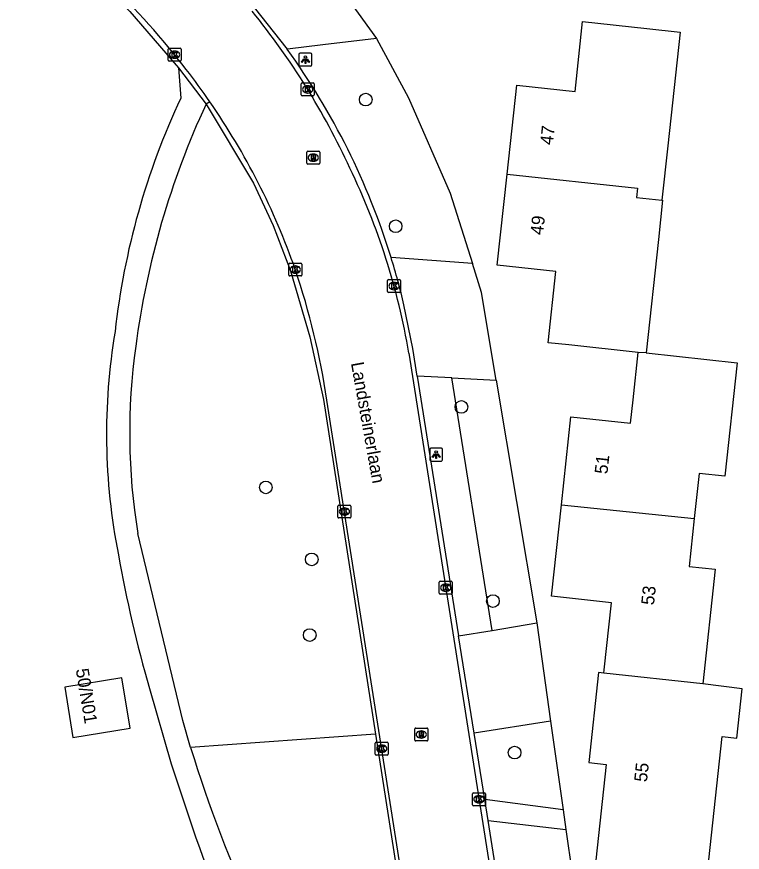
# Model space of a CAD drawing. Extents: x 162157 to 163165, y 378998 to 380775.
# Drawn here: x 162604.5 to 162660.6, y 380304.6 to 380369.3 of the extents above; entities that cross this region are included whole.
import ezdxf

# ---------------------------------------------------------------- set-up
doc = ezdxf.new("R2010")
doc.units = 0
for name, color, linetype in [('IMGEO_Berm_groen', 7, 'Continuous'), ('IMGEO_Boom', 7, 'Continuous'), ('IMGEO_Groenvoorziening', 7, 'Continuous'), ('IMGEO_Kolk', 7, 'Continuous'), ('IMGEO_Lichtpunt', 7, 'Continuous'), ('IMGEO_Naaldbos', 7, 'Continuous'), ('IMGEO_Openbare_ruimte_label', 7, 'Continuous'), ('IMGEO_Pand', 7, 'Continuous'), ('IMGEO_Pand_nummerreeks', 7, 'Continuous'), ('IMGEO_Rijbaan_lokaal_gesloten', 7, 'Continuous'), ('IMGEO_Rioolput', 7, 'Continuous'), ('IMGEO_Voetpad_halfverhard', 7, 'Continuous'), ('IMGEO_Voetpad_open', 7, 'Continuous')]:
    doc.layers.add(name, color=color, linetype=linetype)

msp = doc.modelspace()

# ---------------------------------------------------------------- linework, layer by layer
at = {"layer": 'IMGEO_Berm_groen'}
msp.add_lwpolyline([(162641.266, 380321.775), (162638.135, 380341.3)], dxfattribs=at)
at = {"layer": 'IMGEO_Boom'}
for centre in [(162631.474, 380362.838), (162633.792, 380353.035), (162638.883, 380339.056), (162623.744, 380332.835), (162627.298, 380327.261), (162641.318, 380324.036), (162627.144, 380321.407), (162642.991, 380312.317)]:
    msp.add_circle(centre, 0.489, dxfattribs=at)
at = {"layer": 'IMGEO_Groenvoorziening'}
for points in [[(162632.3, 380367.569), (162634.789, 380362.981), (162638.007, 380355.595), (162639.724, 380350.164)], [(162641.57, 380341.12), (162644.707, 380322.347)], [(162645.784, 380314.752), (162646.759, 380307.877)], [(162646.972, 380306.371), (162647.938, 380299.554)]]:
    msp.add_lwpolyline(points, dxfattribs=at)
at = {"layer": 'IMGEO_Kolk'}
for p, q in [((162616.255, 380366.813), (162617.107, 380366.813)), ((162616.18, 380365.887), (162616.18, 380366.739)), ((162616.668, 380366.593), (162616.693, 380366.593)), ((162617.181, 380366.739), (162617.181, 380365.887)), ((162617.107, 380365.813), (162616.255, 380365.813)), ((162616.691, 380366.033), (162616.666, 380366.033)), ((162626.488, 380363.201), (162626.488, 380364.053)), ((162626.563, 380364.127), (162627.415, 380364.127)), ((162626.976, 380363.907), (162627.001, 380363.907)), ((162627.489, 380364.053), (162627.489, 380363.201)), ((162627.415, 380363.127), (162626.563, 380363.127)), ((162626.999, 380363.347), (162626.974, 380363.347)), ((162625.523, 380349.264), (162625.523, 380350.116)), ((162625.598, 380350.19), (162626.45, 380350.19)), ((162626.524, 380350.116), (162626.524, 380349.264)), ((162626.034, 380349.41), (162626.009, 380349.41)), ((162626.011, 380349.97), (162626.036, 380349.97)), ((162626.45, 380349.19), (162625.598, 380349.19)), ((162633.169, 380347.984), (162633.169, 380348.836)), ((162633.244, 380348.91), (162634.096, 380348.91)), ((162633.657, 380348.69), (162633.682, 380348.69)), ((162634.17, 380348.836), (162634.17, 380347.984)), ((162633.68, 380348.13), (162633.655, 380348.13)), ((162634.096, 380347.91), (162633.244, 380347.91)), ((162629.325, 380330.542), (162629.325, 380331.394)), ((162629.4, 380331.468), (162630.252, 380331.468)), ((162629.813, 380331.248), (162629.838, 380331.248)), ((162630.326, 380331.394), (162630.326, 380330.542)), ((162629.836, 380330.688), (162629.811, 380330.688)), ((162630.252, 380330.468), (162629.4, 380330.468)), ((162637.164, 380324.644), (162637.164, 380325.496)), ((162637.239, 380325.57), (162638.091, 380325.57)), ((162638.165, 380325.496), (162638.165, 380324.644)), ((162637.675, 380324.79), (162637.65, 380324.79)), ((162637.652, 380325.35), (162637.677, 380325.35)), ((162638.091, 380324.57), (162637.239, 380324.57)), ((162632.209, 380312.197), (162632.209, 380313.049)), ((162632.284, 380313.123), (162633.136, 380313.123)), ((162632.697, 380312.903), (162632.722, 380312.903)), ((162633.21, 380313.049), (162633.21, 380312.197)), ((162633.136, 380312.123), (162632.284, 380312.123)), ((162632.72, 380312.343), (162632.695, 380312.343)), ((162639.737, 380308.284), (162639.737, 380309.136)), ((162639.812, 380309.21), (162640.664, 380309.21)), ((162640.225, 380308.99), (162640.25, 380308.99)), ((162640.738, 380309.136), (162640.738, 380308.284)), ((162640.664, 380308.21), (162639.812, 380308.21)), ((162640.248, 380308.43), (162640.223, 380308.43))]:
    msp.add_line(p, q, dxfattribs=at)
for points in [[(162616.255, 380366.813), (162617.107, 380366.813)], [(162616.18, 380365.887), (162616.18, 380366.739)], [(162616.501, 380366.513), (162616.624, 380366.513), (162616.624, 380366.362), (162616.754, 380366.513), (162616.918, 380366.513), (162616.772, 380366.362), (162616.925, 380366.113), (162616.773, 380366.113), (162616.688, 380366.277), (162616.624, 380366.21), (162616.624, 380366.113), (162616.501, 380366.113), (162616.501, 380366.513)], [(162617.181, 380366.739), (162617.181, 380365.887)], [(162617.107, 380365.813), (162616.255, 380365.813)], [(162626.488, 380363.201), (162626.488, 380364.053)], [(162626.563, 380364.127), (162627.415, 380364.127)], [(162626.809, 380363.827), (162626.932, 380363.827), (162626.932, 380363.676), (162627.062, 380363.827), (162627.226, 380363.827), (162627.08, 380363.676), (162627.233, 380363.427), (162627.081, 380363.427), (162626.996, 380363.591), (162626.932, 380363.524), (162626.932, 380363.427), (162626.809, 380363.427), (162626.809, 380363.827)], [(162627.489, 380364.053), (162627.489, 380363.201)], [(162627.415, 380363.127), (162626.563, 380363.127)], [(162625.523, 380349.264), (162625.523, 380350.116)], [(162625.598, 380350.19), (162626.45, 380350.19)], [(162626.524, 380350.116), (162626.524, 380349.264)], [(162625.844, 380349.89), (162625.967, 380349.89), (162625.967, 380349.739), (162626.097, 380349.89), (162626.261, 380349.89), (162626.115, 380349.739), (162626.268, 380349.49), (162626.116, 380349.49), (162626.031, 380349.654), (162625.967, 380349.587), (162625.967, 380349.49), (162625.844, 380349.49), (162625.844, 380349.89)], [(162626.45, 380349.19), (162625.598, 380349.19)], [(162633.169, 380347.984), (162633.169, 380348.836)], [(162633.244, 380348.91), (162634.096, 380348.91)], [(162634.17, 380348.836), (162634.17, 380347.984)], [(162633.49, 380348.61), (162633.613, 380348.61), (162633.613, 380348.459), (162633.743, 380348.61), (162633.907, 380348.61), (162633.761, 380348.459), (162633.914, 380348.21), (162633.762, 380348.21), (162633.677, 380348.374), (162633.613, 380348.307), (162633.613, 380348.21), (162633.49, 380348.21), (162633.49, 380348.61)], [(162634.096, 380347.91), (162633.244, 380347.91)], [(162629.325, 380330.542), (162629.325, 380331.394)], [(162629.4, 380331.468), (162630.252, 380331.468)], [(162630.326, 380331.394), (162630.326, 380330.542)], [(162629.646, 380331.168), (162629.769, 380331.168), (162629.769, 380331.017), (162629.899, 380331.168), (162630.063, 380331.168), (162629.917, 380331.017), (162630.07, 380330.768), (162629.918, 380330.768), (162629.833, 380330.932), (162629.769, 380330.865), (162629.769, 380330.768), (162629.646, 380330.768), (162629.646, 380331.168)], [(162630.252, 380330.468), (162629.4, 380330.468)], [(162637.164, 380324.644), (162637.164, 380325.496)], [(162637.239, 380325.57), (162638.091, 380325.57)], [(162638.165, 380325.496), (162638.165, 380324.644)], [(162637.485, 380325.27), (162637.608, 380325.27), (162637.608, 380325.119), (162637.738, 380325.27), (162637.902, 380325.27), (162637.756, 380325.119), (162637.909, 380324.87), (162637.757, 380324.87), (162637.672, 380325.034), (162637.608, 380324.967), (162637.608, 380324.87), (162637.485, 380324.87), (162637.485, 380325.27)], [(162638.091, 380324.57), (162637.239, 380324.57)], [(162632.209, 380312.197), (162632.209, 380313.049)], [(162632.284, 380313.123), (162633.136, 380313.123)], [(162632.53, 380312.823), (162632.653, 380312.823), (162632.653, 380312.672), (162632.783, 380312.823), (162632.947, 380312.823), (162632.801, 380312.672), (162632.954, 380312.423), (162632.802, 380312.423), (162632.717, 380312.587), (162632.653, 380312.52), (162632.653, 380312.423), (162632.53, 380312.423), (162632.53, 380312.823)], [(162633.21, 380313.049), (162633.21, 380312.197)], [(162633.136, 380312.123), (162632.284, 380312.123)], [(162639.737, 380308.284), (162639.737, 380309.136)], [(162639.812, 380309.21), (162640.664, 380309.21)], [(162640.058, 380308.91), (162640.181, 380308.91), (162640.181, 380308.759), (162640.311, 380308.91), (162640.475, 380308.91), (162640.329, 380308.759), (162640.482, 380308.51), (162640.33, 380308.51), (162640.245, 380308.674), (162640.181, 380308.607), (162640.181, 380308.51), (162640.058, 380308.51), (162640.058, 380308.91)], [(162640.738, 380309.136), (162640.738, 380308.284)], [(162640.664, 380308.21), (162639.812, 380308.21)]]:
    msp.add_lwpolyline(points, dxfattribs=at)
for centre, start, end in [((162616.257, 380366.737), 91.55205, 178.44795), ((162616.257, 380366.737), 91.55205, 178.44795), ((162617.105, 380366.737), 1.55205, 88.44795), ((162617.105, 380366.737), 1.55205, 88.44795), ((162616.257, 380365.889), 181.55205, 268.44795), ((162616.257, 380365.889), 181.55205, 268.44795), ((162617.105, 380365.889), 271.55205, 358.44795), ((162617.105, 380365.889), 271.55205, 358.44795), ((162626.565, 380364.051), 91.55205, 178.44795), ((162626.565, 380364.051), 91.55205, 178.44795), ((162627.413, 380364.051), 1.55205, 88.44795), ((162627.413, 380364.051), 1.55205, 88.44795), ((162626.565, 380363.203), 181.55205, 268.44795), ((162626.565, 380363.203), 181.55205, 268.44795), ((162627.413, 380363.203), 271.55205, 358.44795), ((162627.413, 380363.203), 271.55205, 358.44795), ((162625.6, 380350.114), 91.55205, 178.44795), ((162625.6, 380350.114), 91.55205, 178.44795), ((162626.448, 380350.114), 1.55205, 88.44795), ((162626.448, 380350.114), 1.55205, 88.44795), ((162625.6, 380349.266), 181.55205, 268.44795), ((162625.6, 380349.266), 181.55205, 268.44795), ((162626.448, 380349.266), 271.55205, 358.44795), ((162626.448, 380349.266), 271.55205, 358.44795), ((162633.246, 380348.834), 91.55205, 178.44795), ((162633.246, 380348.834), 91.55205, 178.44795), ((162634.094, 380348.834), 1.55205, 88.44795), ((162634.094, 380348.834), 1.55205, 88.44795), ((162633.246, 380347.986), 181.55205, 268.44795), ((162633.246, 380347.986), 181.55205, 268.44795), ((162634.094, 380347.986), 271.55205, 358.44795), ((162634.094, 380347.986), 271.55205, 358.44795), ((162629.402, 380331.392), 91.55205, 178.44795), ((162629.402, 380331.392), 91.55205, 178.44795), ((162630.25, 380331.392), 1.55205, 88.44795), ((162630.25, 380331.392), 1.55205, 88.44795), ((162629.402, 380330.544), 181.55205, 268.44795), ((162629.402, 380330.544), 181.55205, 268.44795), ((162630.25, 380330.544), 271.55205, 358.44795), ((162630.25, 380330.544), 271.55205, 358.44795), ((162637.241, 380325.494), 91.55205, 178.44795), ((162637.241, 380325.494), 91.55205, 178.44795), ((162638.089, 380325.494), 1.55205, 88.44795), ((162638.089, 380325.494), 1.55205, 88.44795), ((162637.241, 380324.646), 181.55205, 268.44795), ((162637.241, 380324.646), 181.55205, 268.44795), ((162638.089, 380324.646), 271.55205, 358.44795), ((162638.089, 380324.646), 271.55205, 358.44795), ((162632.286, 380313.047), 91.55205, 178.44795), ((162632.286, 380313.047), 91.55205, 178.44795), ((162633.134, 380313.047), 1.55205, 88.44795), ((162633.134, 380313.047), 1.55205, 88.44795), ((162632.286, 380312.199), 181.55205, 268.44795), ((162632.286, 380312.199), 181.55205, 268.44795), ((162633.134, 380312.199), 271.55205, 358.44795), ((162633.134, 380312.199), 271.55205, 358.44795), ((162639.814, 380309.134), 91.55205, 178.44795), ((162639.814, 380309.134), 91.55205, 178.44795), ((162640.662, 380309.134), 1.55205, 88.44795), ((162640.662, 380309.134), 1.55205, 88.44795), ((162639.814, 380308.286), 181.55205, 268.44795), ((162639.814, 380308.286), 181.55205, 268.44795), ((162640.662, 380308.286), 271.55205, 358.44795), ((162640.662, 380308.286), 271.55205, 358.44795)]:
    msp.add_arc(centre, 0.0765, start, end, dxfattribs=at)
for centre, major_axis, ratio, start_param, end_param in [((162616.667, 380366.313), (-0.387, 0.002), 0.722429, 4.712389, 7.853982), ((162616.692, 380366.313), (-0.39, 0.002), 0.717154, 1.570796, 4.712389), ((162626.975, 380363.627), (-0.387, 0.002), 0.722429, 4.712389, 7.853982), ((162627, 380363.627), (-0.39, 0.002), 0.717154, 1.570796, 4.712389), ((162626.01, 380349.69), (-0.387, 0.002), 0.722429, 4.712389, 7.853982), ((162626.035, 380349.69), (-0.39, 0.002), 0.717154, 1.570796, 4.712389), ((162633.656, 380348.41), (-0.387, 0.002), 0.722429, 4.712389, 7.853982), ((162633.681, 380348.41), (-0.39, 0.002), 0.717154, 1.570796, 4.712389), ((162629.812, 380330.968), (-0.387, 0.002), 0.722429, 4.712389, 7.853982), ((162629.837, 380330.968), (-0.39, 0.002), 0.717154, 1.570796, 4.712389), ((162637.651, 380325.07), (-0.387, 0.002), 0.722429, 4.712389, 7.853982), ((162637.676, 380325.07), (-0.39, 0.002), 0.717154, 1.570796, 4.712389), ((162632.696, 380312.623), (-0.387, 0.002), 0.722429, 4.712389, 7.853982), ((162632.721, 380312.623), (-0.39, 0.002), 0.717154, 1.570796, 4.712389), ((162640.224, 380308.71), (-0.387, 0.002), 0.722429, 4.712389, 7.853982), ((162640.249, 380308.71), (-0.39, 0.002), 0.717154, 1.570796, 4.712389)]:
    msp.add_ellipse(centre, major_axis=major_axis, ratio=ratio, start_param=start_param, end_param=end_param, dxfattribs=at)
at = {"layer": 'IMGEO_Lichtpunt'}
for p, q in [((162626.306, 380366.338), (162626.306, 380365.531)), ((162626.306, 380366.338), (162626.306, 380365.531)), ((162627.208, 380366.433), (162626.4, 380366.433)), ((162627.208, 380366.433), (162626.4, 380366.433)), ((162627.302, 380365.531), (162627.302, 380366.338)), ((162627.302, 380365.531), (162627.302, 380366.338)), ((162626.4, 380365.437), (162627.208, 380365.437)), ((162626.4, 380365.437), (162627.208, 380365.437)), ((162636.431, 380335.777), (162636.431, 380334.97)), ((162636.431, 380335.777), (162636.431, 380334.97)), ((162637.333, 380335.872), (162636.525, 380335.872)), ((162637.333, 380335.872), (162636.525, 380335.872)), ((162637.427, 380334.97), (162637.427, 380335.777)), ((162637.427, 380334.97), (162637.427, 380335.777)), ((162636.525, 380334.876), (162637.333, 380334.876)), ((162636.525, 380334.876), (162637.333, 380334.876))]:
    msp.add_line(p, q, dxfattribs=at)
for points in [[(162626.68, 380366.002), (162626.719, 380365.974), (162626.531, 380365.712), (162626.493, 380365.739), (162626.68, 380366.002)], [(162626.782, 380365.954), (162626.829, 380365.954), (162626.829, 380365.632), (162626.782, 380365.632), (162626.782, 380365.954)], [(162626.892, 380365.974), (162626.93, 380366.001), (162627.117, 380365.739), (162627.078, 380365.711), (162626.892, 380365.974)], [(162636.805, 380335.441), (162636.844, 380335.413), (162636.656, 380335.151), (162636.618, 380335.178), (162636.805, 380335.441)], [(162636.907, 380335.393), (162636.954, 380335.393), (162636.954, 380335.071), (162636.907, 380335.071), (162636.907, 380335.393)], [(162637.017, 380335.413), (162637.055, 380335.44), (162637.242, 380335.178), (162637.203, 380335.15), (162637.017, 380335.413)]]:
    msp.add_lwpolyline(points, dxfattribs=at)
for centre in [(162626.805, 380366.136), (162636.93, 380335.575)]:
    msp.add_circle(centre, 0.0994, dxfattribs=at)
for centre, start, end in [((162626.4, 380366.338), 90, 180), ((162626.4, 380366.338), 90, 180), ((162627.208, 380366.338), 0, 90), ((162627.208, 380366.338), 0, 90), ((162626.4, 380365.531), 180, 270), ((162626.4, 380365.531), 180, 270), ((162627.208, 380365.531), 270, 0), ((162627.208, 380365.531), 270, 360), ((162636.525, 380335.777), 90, 180), ((162636.525, 380335.777), 90, 180), ((162637.333, 380335.777), 0, 90), ((162637.333, 380335.777), 0, 90), ((162636.525, 380334.97), 180, 270), ((162636.525, 380334.97), 180, 270), ((162637.333, 380334.97), 270, 0), ((162637.333, 380334.97), 270, 360)]:
    msp.add_arc(centre, 0.0946, start, end, dxfattribs=at)
at = {"layer": 'IMGEO_Naaldbos'}
msp.add_lwpolyline([(162632.237, 380313.739), (162617.926, 380312.706)], dxfattribs=at)
at = {"layer": 'IMGEO_Pand'}
for points in [[(162642.409, 380357.068), (162643.155, 380363.948), (162647.669, 380363.459), (162648.256, 380368.88), (162653.227, 380368.341), (162655.803, 380368.062), (162654.848, 380359.25), (162654.393, 380355.053)], [(162652.566, 380343.271), (162647.186, 380343.854), (162645.595, 380344.026), (162646.192, 380349.53), (162641.646, 380350.022), (162642.409, 380357.068)], [(162642.409, 380357.068), (162652.511, 380355.991), (162652.432, 380355.265), (162654.393, 380355.053)], [(162654.393, 380355.053), (162654.448, 380355.047), (162654.12, 380352.023), (162653.168, 380343.235)], [(162646.62, 380331.493), (162647.357, 380338.293), (162651.973, 380337.793), (162652.17, 380339.613), (162652.566, 380343.271)], [(162653.168, 380343.235), (162652.566, 380343.271)], [(162653.168, 380343.235), (162660.211, 380342.472), (162659.261, 380333.696), (162657.27, 380333.911), (162656.892, 380330.426)], [(162649.908, 380318.461), (162649.936, 380318.722), (162650.498, 380323.905), (162645.852, 380324.408), (162646.62, 380331.493)], [(162646.62, 380331.493), (162656.892, 380330.426)], [(162656.892, 380330.426), (162656.491, 380326.726), (162658.509, 380326.508), (162657.549, 380317.645)], [(162649.908, 380318.461), (162649.487, 380318.506), (162648.733, 380311.549), (162650.084, 380311.403), (162649.282, 380303.995), (162653.155, 380303.576)], [(162657.549, 380317.645), (162649.908, 380318.461)], [(162608.821, 380313.488), (162613.237, 380314.211), (162612.601, 380318.095), (162608.185, 380317.371), (162608.821, 380313.488)], [(162657.097, 380303.149), (162657.925, 380303.059), (162659.061, 380313.55), (162660.2, 380313.426), (162660.615, 380317.262), (162657.549, 380317.645)]]:
    msp.add_lwpolyline(points, dxfattribs=at)
at = {"layer": 'IMGEO_Rijbaan_lokaal_gesloten'}
for points in [[(162609.857, 380372.928), (162613.229, 380369.661), (162616.988, 380365.303)], [(162625.408, 380366.729), (162620.408, 380373.079)], [(162616.988, 380365.303), (162619.115, 380362.472)], [(162619.409, 380362.676), (162619.115, 380362.472)], [(162619.115, 380362.472), (162622.798, 380356.374), (162624.3, 380353.107), (162625.663, 380349.6), (162627.136, 380344.494), (162628.212, 380339.639), (162632.237, 380313.739)], [(162635.453, 380341.441), (162635.11, 380343.59), (162634.429, 380346.968)], [(162634.809, 380343.221), (162645.535, 380275.023)], [(162635.453, 380341.441), (162638.665, 380321.343)], [(162639.061, 380272.234), (162628.472, 380339.591)], [(162639.868, 380313.815), (162638.665, 380321.343)], [(162640.689, 380308.679), (162639.868, 380313.815)], [(162632.237, 380313.739), (162638.257, 380274.994)], [(162640.948, 380307.056), (162640.689, 380308.679)], [(162642.043, 380300.207), (162640.948, 380307.056)]]:
    msp.add_lwpolyline(points, dxfattribs=at)
for centre, radius, start, end in [((162572.012, 380330.389), 57.323, 37.33599, 55.51814), ((162579.31, 380334.234), 56.01, 24.58124, 39.25461), ((162580.382, 380334.232), 55.528, 17.17332, 35.82007), ((162575.007, 380331.985), 53.977, 34.65243, 37.91734), ((162574.553, 380331.645), 54.543, 19.31623, 34.67518), ((162582.721, 380334.491), 52.815, 9.51453, 25.867), ((162581.867, 380334.654), 53.985, 13.18566, 17.2106), ((162569.176, 380330.569), 59.978, 8.6509, 18.58684)]:
    msp.add_arc(centre, radius, start, end, dxfattribs=at)
at = {"layer": 'IMGEO_Rioolput'}
for p, q in [((162626.913, 380357.916), (162626.913, 380358.768)), ((162626.988, 380358.842), (162627.84, 380358.842)), ((162627.401, 380358.622), (162627.426, 380358.622)), ((162627.914, 380358.768), (162627.914, 380357.916)), ((162627.84, 380357.842), (162626.988, 380357.842)), ((162627.424, 380358.062), (162627.399, 380358.062)), ((162635.269, 380313.29), (162635.269, 380314.142)), ((162635.344, 380314.216), (162636.196, 380314.216)), ((162635.757, 380313.996), (162635.782, 380313.996)), ((162636.27, 380314.142), (162636.27, 380313.29)), ((162636.196, 380313.216), (162635.344, 380313.216)), ((162635.78, 380313.436), (162635.755, 380313.436))]:
    msp.add_line(p, q, dxfattribs=at)
for points in [[(162626.913, 380357.916), (162626.913, 380358.768)], [(162626.988, 380358.842), (162627.84, 380358.842)], [(162627.502, 380358.54), (162627.25, 380358.542), (162627.25, 380358.142)], [(162627.428, 380358.461), (162627.374, 380358.461), (162627.374, 380358.38)], [(162627.914, 380358.768), (162627.914, 380357.916)], [(162627.84, 380357.842), (162626.988, 380357.842)], [(162627.25, 380358.142), (162627.374, 380358.142), (162627.374, 380358.304), (162627.385, 380358.304)], [(162627.374, 380358.38), (162627.426, 380358.38)], [(162627.432, 380358.275), (162627.503, 380358.142), (162627.643, 380358.142), (162627.578, 380358.268)], [(162635.269, 380313.29), (162635.269, 380314.142)], [(162635.344, 380314.216), (162636.196, 380314.216)], [(162635.858, 380313.914), (162635.606, 380313.916), (162635.606, 380313.516)], [(162635.784, 380313.835), (162635.73, 380313.835), (162635.73, 380313.754)], [(162636.27, 380314.142), (162636.27, 380313.29)], [(162636.196, 380313.216), (162635.344, 380313.216)], [(162635.606, 380313.516), (162635.73, 380313.516), (162635.73, 380313.678), (162635.741, 380313.678)], [(162635.73, 380313.754), (162635.782, 380313.754)], [(162635.788, 380313.649), (162635.859, 380313.516), (162635.999, 380313.516), (162635.934, 380313.642)]]:
    msp.add_lwpolyline(points, dxfattribs=at)
for centre, radius, start, end in [((162626.99, 380358.766), 0.0765, 91.55205, 178.44795), ((162626.99, 380358.766), 0.0765, 91.55205, 178.44795), ((162627.41, 380358.569), 0.19, 274.7715, 282.96867), ((162627.434, 380358.365), 0.0964, 77.00612, 93.18647), ((162627.448, 380358.422), 0.0378, 276.66336, 79.67722), ((162627.501, 380358.43), 0.109, 350.36119, 89.41601), ((162627.499, 380358.43), 0.112, 277.58423, 350.98172), ((162627.838, 380358.766), 0.0765, 1.55205, 88.44795), ((162627.838, 380358.766), 0.0765, 1.55205, 88.44795), ((162626.99, 380357.918), 0.0765, 181.55205, 268.44795), ((162626.99, 380357.918), 0.0765, 181.55205, 268.44795), ((162627.384, 380358.251), 0.0533, 26.02933, 88.69889), ((162627.483, 380358.215), 0.108, 29.51342, 73.79051), ((162627.838, 380357.918), 0.0765, 271.55205, 358.44795), ((162627.838, 380357.918), 0.0765, 271.55205, 358.44795), ((162635.346, 380314.14), 0.0765, 91.55205, 178.44795), ((162635.346, 380314.14), 0.0765, 91.55205, 178.44795), ((162635.79, 380313.739), 0.0964, 77.00612, 93.18647), ((162635.804, 380313.796), 0.0378, 276.66336, 79.67722), ((162635.857, 380313.804), 0.109, 350.36119, 89.41601), ((162635.855, 380313.804), 0.112, 277.58423, 350.98172), ((162636.194, 380314.14), 0.0765, 1.55205, 88.44795), ((162636.194, 380314.14), 0.0765, 1.55205, 88.44795), ((162635.346, 380313.292), 0.0765, 181.55205, 268.44795), ((162635.346, 380313.292), 0.0765, 181.55205, 268.44795), ((162635.74, 380313.625), 0.0533, 26.02933, 88.69889), ((162635.766, 380313.943), 0.19, 274.7715, 282.96867), ((162635.839, 380313.589), 0.108, 29.51342, 73.79051), ((162636.194, 380313.292), 0.0765, 271.55205, 358.44795), ((162636.194, 380313.292), 0.0765, 271.55205, 358.44795)]:
    msp.add_arc(centre, radius, start, end, dxfattribs=at)
for centre, major_axis, ratio, start_param, end_param in [((162627.4, 380358.342), (-0.387, 0.002), 0.722429, 4.712389, 7.853982), ((162627.425, 380358.342), (-0.39, 0.002), 0.717154, 1.570796, 4.712389), ((162635.756, 380313.716), (-0.387, 0.002), 0.722429, 4.712389, 7.853982), ((162635.781, 380313.716), (-0.39, 0.002), 0.717154, 1.570796, 4.712389)]:
    msp.add_ellipse(centre, major_axis=major_axis, ratio=ratio, start_param=start_param, end_param=end_param, dxfattribs=at)
at = {"layer": 'IMGEO_Voetpad_halfverhard'}
for points in [[(162616.988, 380365.303), (162617.159, 380362.954)], [(162617.926, 380312.706), (162617.31, 380314.804), (162613.837, 380329.262)], [(162614.738, 380317.273), (162616.417, 380311.455), (162618.332, 380305.71)]]:
    msp.add_lwpolyline(points, dxfattribs=at)
for centre, radius, start, end in [((162669.3, 380338.545), 57.572, 154.91464, 173.66698), ((162677.372, 380335.403), 64.239, 155.07841, 172.53426), ((162659.181, 380336.958), 47.765, 170.43356, 191.26505), ((162661.407, 380337.029), 48.2, 171.9844, 189.27314), ((162713.489, 380345.638), 102.744, 190.09591, 196.02585), ((162714.705, 380342.304), 101.204, 197.00537, 205.02665), ((162669.319, 380323.454), 53.986, 199.18825, 212.60959)]:
    msp.add_arc(centre, radius, start, end, dxfattribs=at)
at = {"layer": 'IMGEO_Voetpad_open'}
for points in [[(162627.512, 380374.217), (162632.3, 380367.569)], [(162632.3, 380367.569), (162628.15, 380367.063), (162625.408, 380366.729)], [(162639.724, 380350.164), (162633.435, 380350.627)], [(162641.57, 380341.12), (162640.435, 380347.913), (162639.724, 380350.164)], [(162638.135, 380341.3), (162635.453, 380341.441)], [(162638.135, 380341.3), (162641.57, 380341.12)], [(162641.266, 380321.775), (162644.707, 380322.347)], [(162644.707, 380322.347), (162645.784, 380314.752)], [(162638.665, 380321.343), (162641.266, 380321.775)], [(162645.784, 380314.752), (162639.868, 380313.815)], [(162646.759, 380307.877), (162640.689, 380308.679)], [(162646.759, 380307.877), (162646.972, 380306.371)], [(162640.948, 380307.056), (162646.972, 380306.371)]]:
    msp.add_lwpolyline(points, dxfattribs=at)

# ---------------------------------------------------------------- texts
at = {"layer": 'IMGEO_Openbare_ruimte_label'}
msp.add_text('Landsteinerlaan', height=1, rotation=280.19721, dxfattribs=at).set_placement((162630.326, 380342.449))
at = {"layer": 'IMGEO_Pand_nummerreeks'}
for s, rotation, p in [('47', 83.818, (162645.949, 380359.292)), ('49', 83.818, (162645.194, 380352.329)), ('51', 83.81384, (162650.173, 380333.83)), ('53', 83.81227, (162653.773, 380323.691)), ('50/N01', 279.46232, (162609.028, 380318.747)), ('55', 83.82373, (162653.231, 380310.004))]:
    msp.add_text(s, height=1, rotation=rotation, dxfattribs=at).set_placement(p)

doc.saveas('drawing.dxf')
